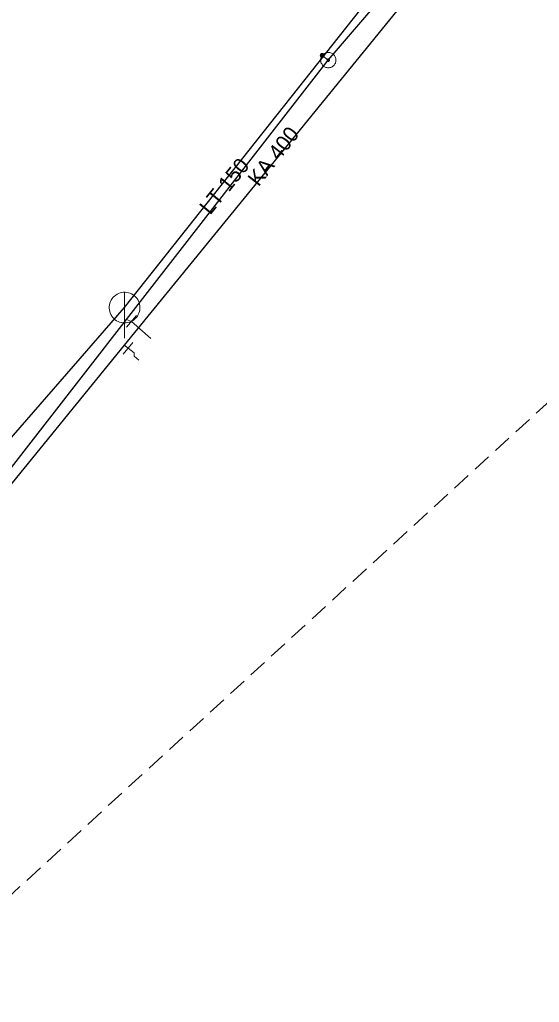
# Model space of a CAD drawing. Extents: x -790267 to -789874, y -989766 to -989454.
# Drawn here: x -790004.3 to -789970.5, y -989730.1 to -989666 of the extents above; entities that cross this region are included whole.
import ezdxf

# ---------------------------------------------------------------- set-up
doc = ezdxf.new("R2010")
doc.units = 0
doc.header["$LTSCALE"] = 0.4
doc.linetypes.add('MEDIUM_DASHED', pattern=[4.5, 3, -1.5])
doc.layers.add('1', color=7, linetype='Continuous')
for name, color, linetype, lineweight in [('13', 7, 'Continuous', 13), ('14', 7, 'Continuous', 13), ('17', 7, 'Continuous', 25), ('22', 7, 'Continuous', 13), ('34', 7, 'Continuous', 13), ('47', 7, 'Continuous', 13), ('63', 7, 'MEDIUM_DASHED', 25), ('9', 7, 'Continuous', 13)]:
    doc.layers.add(name, color=color, linetype=linetype, lineweight=lineweight)

msp = doc.modelspace()

# ---------------------------------------------------------------- linework, layer by layer
at = {"layer": '13'}
for points in [[(-789997.342, -989685.576), (-789997.024, -989685.702), (-789995.752, -989686.822)], [(-789997.247, -989687.449), (-789996.85, -989687.75), (-789996.85, -989687.96), (-789996.55, -989688.219)]]:
    msp.add_lwpolyline(points, dxfattribs=at)
at = {"layer": '14'}
for p, q in [((-789984.21, -989668.683), (-789984.603, -989668.375)), ((-789997.491, -989687.245), (-789997.247, -989687.449))]:
    msp.add_line(p, q, dxfattribs=at)
at = {"layer": '14', "lineweight": 25}
msp.add_lwpolyline([(-790015.27, -989747.72), (-790017.28, -989707.56), (-789997.47, -989684.8), (-789979.42, -989661.98), (-789971.89, -989652.27)], dxfattribs=at)
at = {"layer": '17'}
for points in [[(-789984.21, -989668.683), (-789974.678, -989657.539), (-789933.135, -989608.969)], [(-789973.42, -989657.67), (-789975.664, -989660.431), (-789977.556, -989662.759), (-789987.276, -989674.721), (-789997.491, -989687.245), (-790005.072, -989696.559), (-790016.278, -989710.509), (-790018.158, -989712.846), (-790025.949, -989722.546), (-790026.25, -989722.92), (-790028.329, -989725.546), (-790029.004, -989726.397), (-790029.656, -989727.219)], [(-790016.192, -989709.824), (-789997.342, -989685.576), (-789984.21, -989668.683)]]:
    msp.add_lwpolyline(points, dxfattribs=at)
at = {"layer": '22'}
msp.add_line((-789997.47, -989686.8), (-789997.469, -989683.8), dxfattribs=at)
msp.add_lwpolyline([(-789996.47, -989684.8), (-789996.475, -989684.691), (-789996.493, -989684.583), (-789996.523, -989684.477), (-789996.563, -989684.376), (-789996.615, -989684.279), (-789996.677, -989684.189), (-789996.749, -989684.106), (-789996.829, -989684.032), (-789996.917, -989683.966), (-789997.011, -989683.911), (-789997.111, -989683.866), (-789997.216, -989683.833), (-789997.323, -989683.811), (-789997.432, -989683.801), (-789997.542, -989683.803), (-789997.65, -989683.817), (-789997.757, -989683.842), (-789997.86, -989683.879), (-789997.958, -989683.928), (-789998.05, -989683.986), (-789998.136, -989684.055), (-789998.213, -989684.132), (-789998.282, -989684.218), (-789998.341, -989684.31), (-789998.389, -989684.408), (-789998.426, -989684.511), (-789998.452, -989684.618), (-789998.466, -989684.726), (-789998.469, -989684.836), (-789998.459, -989684.945), (-789998.438, -989685.052), (-789998.404, -989685.156), (-789998.36, -989685.256), (-789998.305, -989685.351), (-789998.239, -989685.439), (-789998.165, -989685.519), (-789998.082, -989685.591), (-789997.992, -989685.653), (-789997.896, -989685.705), (-789997.794, -989685.746), (-789997.689, -989685.776), (-789997.581, -989685.794), (-789997.471, -989685.8), (-789997.362, -989685.794), (-789997.254, -989685.776), (-789997.149, -989685.747), (-789997.047, -989685.706), (-789996.95, -989685.654), (-789996.86, -989685.592), (-789996.777, -989685.521), (-789996.702, -989685.441), (-789996.637, -989685.353), (-789996.581, -989685.259), (-789996.537, -989685.159), (-789996.503, -989685.055), (-789996.481, -989684.947), (-789996.471, -989684.838)], close=True, dxfattribs=at)
at = {"layer": '34'}
for p, q in [((-789996.693, -989685.326), (-789997.354, -989686.076)), ((-789996.927, -989687.064), (-789997.567, -989687.833))]:
    msp.add_line(p, q, dxfattribs=at)
at = {"layer": '47'}
for points in [[(-789983.918, -989668.276), (-789983.962, -989668.249), (-789984.009, -989668.225), (-789984.057, -989668.207), (-789984.108, -989668.193), (-789984.16, -989668.185), (-789984.213, -989668.183), (-789984.264, -989668.186), (-789984.316, -989668.195), (-789984.366, -989668.208), (-789984.415, -989668.227), (-789984.462, -989668.251), (-789984.505, -989668.28), (-789984.546, -989668.313), (-789984.583, -989668.35), (-789984.616, -989668.391), (-789984.643, -989668.435), (-789984.667, -989668.482), (-789984.686, -989668.531), (-789984.699, -989668.581), (-789984.707, -989668.633), (-789984.709, -989668.686), (-789984.706, -989668.738), (-789984.698, -989668.79), (-789984.685, -989668.84), (-789984.665, -989668.888), (-789984.641, -989668.935), (-789984.612, -989668.979), (-789984.579, -989669.019), (-789984.542, -989669.056), (-789984.501, -989669.089), (-789984.457, -989669.116), (-789984.41, -989669.14), (-789984.361, -989669.16), (-789984.311, -989669.172), (-789984.259, -989669.18), (-789984.207, -989669.183), (-789984.155, -989669.18), (-789984.103, -989669.172), (-789984.052, -989669.158), (-789984.004, -989669.138), (-789983.957, -989669.114), (-789983.913, -989669.086), (-789983.873, -989669.052), (-789983.836, -989669.015), (-789983.803, -989668.974), (-789983.776, -989668.93), (-789983.752, -989668.883), (-789983.733, -989668.835), (-789983.72, -989668.784), (-789983.712, -989668.732), (-789983.709, -989668.68), (-789983.713, -989668.628), (-789983.721, -989668.577), (-789983.735, -989668.526), (-789983.754, -989668.477), (-789983.778, -989668.43), (-789983.806, -989668.387), (-789983.84, -989668.346), (-789983.877, -989668.309)], [(-789984.162, -989668.616), (-789984.169, -989668.611), (-789984.177, -989668.608), (-789984.184, -989668.605), (-789984.193, -989668.602), (-789984.201, -989668.601), (-789984.21, -989668.601), (-789984.219, -989668.601), (-789984.227, -989668.602), (-789984.235, -989668.605), (-789984.243, -989668.608), (-789984.251, -989668.612), (-789984.258, -989668.617), (-789984.265, -989668.622), (-789984.271, -989668.627), (-789984.276, -989668.635), (-789984.281, -989668.642), (-789984.284, -989668.65), (-789984.287, -989668.657), (-789984.29, -989668.666), (-789984.291, -989668.674), (-789984.291, -989668.683), (-789984.291, -989668.692), (-789984.29, -989668.7), (-789984.288, -989668.709), (-789984.284, -989668.716), (-789984.28, -989668.724), (-789984.275, -989668.731), (-789984.27, -989668.738), (-789984.265, -989668.744), (-789984.257, -989668.749), (-789984.25, -989668.754), (-789984.242, -989668.757), (-789984.235, -989668.76), (-789984.226, -989668.763), (-789984.218, -989668.764), (-789984.21, -989668.765), (-789984.2, -989668.764), (-789984.192, -989668.763), (-789984.183, -989668.761), (-789984.176, -989668.757), (-789984.168, -989668.753), (-789984.161, -989668.748), (-789984.154, -989668.743), (-789984.148, -989668.738), (-789984.143, -989668.73), (-789984.138, -989668.723), (-789984.135, -989668.715), (-789984.132, -989668.708), (-789984.129, -989668.699), (-789984.128, -989668.691), (-789984.127, -989668.683), (-789984.128, -989668.673), (-789984.129, -989668.665), (-789984.132, -989668.657), (-789984.135, -989668.649), (-789984.139, -989668.641), (-789984.144, -989668.634), (-789984.149, -989668.627), (-789984.154, -989668.621)]]:
    msp.add_lwpolyline(points, close=True, dxfattribs=at)
at = {"layer": '63'}
msp.add_lwpolyline([(-790188.469, -989455.136), (-790139.344, -989496.446), (-790139.344, -989496.446), (-790029.929, -989518.217), (-790029.929, -989518.217), (-789963.498, -989555.061), (-789963.498, -989555.061), (-789946.75, -989559.527), (-789946.75, -989559.527), (-789908.79, -989634.89), (-789908.79, -989634.89), (-790051.142, -989765.519), (-790051.142, -989765.519), (-790157.208, -989714.719), (-790157.208, -989714.719), (-790153.3, -989672.851), (-790153.3, -989672.851), (-790266.065, -989576.274), (-790266.065, -989576.274), (-790235.362, -989502.586), (-790235.362, -989502.586), (-790189.028, -989455.694), (-790189.028, -989455.694)], close=True, dxfattribs=at)
at = {"layer": '9'}
for points in [[(-789984.729, -989668.375), (-789984.729, -989668.388), (-789984.727, -989668.401), (-789984.724, -989668.414), (-789984.719, -989668.426), (-789984.713, -989668.438), (-789984.706, -989668.449), (-789984.698, -989668.459), (-789984.688, -989668.469), (-789984.678, -989668.477), (-789984.667, -989668.484), (-789984.655, -989668.49), (-789984.643, -989668.495), (-789984.63, -989668.498), (-789984.617, -989668.5), (-789984.604, -989668.502), (-789984.591, -989668.501), (-789984.578, -989668.499), (-789984.565, -989668.496), (-789984.553, -989668.491), (-789984.541, -989668.485), (-789984.53, -989668.478), (-789984.52, -989668.47), (-789984.51, -989668.46), (-789984.502, -989668.45), (-789984.495, -989668.439), (-789984.489, -989668.427), (-789984.484, -989668.415), (-789984.481, -989668.402), (-789984.479, -989668.389), (-789984.477, -989668.376), (-789984.478, -989668.363), (-789984.48, -989668.35), (-789984.483, -989668.337), (-789984.488, -989668.325), (-789984.494, -989668.313), (-789984.501, -989668.302), (-789984.509, -989668.292), (-789984.519, -989668.282), (-789984.529, -989668.274), (-789984.54, -989668.267), (-789984.552, -989668.261), (-789984.564, -989668.256), (-789984.577, -989668.253), (-789984.59, -989668.251), (-789984.603, -989668.25), (-789984.616, -989668.25), (-789984.629, -989668.252), (-789984.642, -989668.255), (-789984.654, -989668.26), (-789984.666, -989668.266), (-789984.677, -989668.273), (-789984.687, -989668.281), (-789984.697, -989668.291), (-789984.705, -989668.301), (-789984.712, -989668.312), (-789984.718, -989668.324), (-789984.723, -989668.336), (-789984.726, -989668.349), (-789984.728, -989668.362)], [(-789984.709, -989668.375), (-789984.71, -989668.386), (-789984.708, -989668.397), (-789984.705, -989668.408), (-789984.701, -989668.418), (-789984.696, -989668.428), (-789984.69, -989668.437), (-789984.683, -989668.446), (-789984.675, -989668.454), (-789984.666, -989668.461), (-789984.657, -989668.467), (-789984.647, -989668.472), (-789984.637, -989668.476), (-789984.626, -989668.479), (-789984.615, -989668.482), (-789984.604, -989668.482), (-789984.593, -989668.482), (-789984.582, -989668.48), (-789984.571, -989668.477), (-789984.561, -989668.473), (-789984.551, -989668.468), (-789984.542, -989668.462), (-789984.533, -989668.455), (-789984.525, -989668.447), (-789984.518, -989668.438), (-789984.512, -989668.429), (-789984.507, -989668.419), (-789984.503, -989668.409), (-789984.5, -989668.398), (-789984.498, -989668.387), (-789984.497, -989668.376), (-789984.497, -989668.365), (-789984.499, -989668.354), (-789984.502, -989668.343), (-789984.506, -989668.333), (-789984.511, -989668.323), (-789984.517, -989668.314), (-789984.524, -989668.305), (-789984.532, -989668.297), (-789984.541, -989668.29), (-789984.55, -989668.284), (-789984.56, -989668.279), (-789984.57, -989668.275), (-789984.581, -989668.272), (-789984.592, -989668.27), (-789984.603, -989668.27), (-789984.614, -989668.269), (-789984.625, -989668.271), (-789984.636, -989668.274), (-789984.646, -989668.278), (-789984.656, -989668.283), (-789984.665, -989668.289), (-789984.674, -989668.296), (-789984.682, -989668.304), (-789984.689, -989668.313), (-789984.695, -989668.322), (-789984.7, -989668.332), (-789984.704, -989668.342), (-789984.707, -989668.353), (-789984.709, -989668.364)], [(-789984.69, -989668.375), (-789984.69, -989668.384), (-789984.689, -989668.393), (-789984.686, -989668.402), (-789984.683, -989668.41), (-789984.679, -989668.418), (-789984.674, -989668.426), (-789984.668, -989668.433), (-789984.662, -989668.439), (-789984.655, -989668.445), (-789984.647, -989668.45), (-789984.639, -989668.454), (-789984.631, -989668.457), (-789984.622, -989668.46), (-789984.613, -989668.461), (-789984.604, -989668.463), (-789984.595, -989668.462), (-789984.586, -989668.461), (-789984.577, -989668.458), (-789984.569, -989668.455), (-789984.561, -989668.451), (-789984.553, -989668.446), (-789984.546, -989668.44), (-789984.54, -989668.434), (-789984.534, -989668.427), (-789984.529, -989668.419), (-789984.525, -989668.411), (-789984.522, -989668.403), (-789984.519, -989668.394), (-789984.518, -989668.385), (-789984.516, -989668.376), (-789984.517, -989668.367), (-789984.518, -989668.358), (-789984.521, -989668.349), (-789984.524, -989668.341), (-789984.528, -989668.333), (-789984.533, -989668.325), (-789984.539, -989668.318), (-789984.545, -989668.312), (-789984.552, -989668.306), (-789984.56, -989668.301), (-789984.568, -989668.297), (-789984.576, -989668.294), (-789984.585, -989668.291), (-789984.594, -989668.29), (-789984.603, -989668.289), (-789984.612, -989668.289), (-789984.621, -989668.29), (-789984.63, -989668.293), (-789984.638, -989668.296), (-789984.646, -989668.3), (-789984.654, -989668.305), (-789984.661, -989668.311), (-789984.667, -989668.317), (-789984.673, -989668.324), (-789984.678, -989668.332), (-789984.682, -989668.34), (-789984.685, -989668.348), (-789984.688, -989668.357), (-789984.689, -989668.366)], [(-789984.67, -989668.375), (-789984.67, -989668.382), (-789984.669, -989668.389), (-789984.668, -989668.396), (-789984.665, -989668.402), (-789984.662, -989668.408), (-789984.658, -989668.414), (-789984.654, -989668.42), (-789984.649, -989668.425), (-789984.643, -989668.429), (-789984.637, -989668.433), (-789984.631, -989668.436), (-789984.625, -989668.439), (-789984.618, -989668.44), (-789984.611, -989668.443), (-789984.604, -989668.443), (-789984.597, -989668.443), (-789984.59, -989668.441), (-789984.583, -989668.44), (-789984.577, -989668.437), (-789984.57, -989668.434), (-789984.565, -989668.43), (-789984.559, -989668.426), (-789984.554, -989668.421), (-789984.55, -989668.415), (-789984.546, -989668.409), (-789984.543, -989668.403), (-789984.54, -989668.397), (-789984.538, -989668.39), (-789984.537, -989668.383), (-789984.536, -989668.376), (-789984.536, -989668.369), (-789984.537, -989668.362), (-789984.539, -989668.355), (-789984.542, -989668.349), (-789984.545, -989668.342), (-789984.549, -989668.337), (-789984.553, -989668.331), (-789984.558, -989668.326), (-789984.564, -989668.322), (-789984.569, -989668.318), (-789984.576, -989668.315), (-789984.582, -989668.312), (-789984.589, -989668.31), (-789984.596, -989668.309), (-789984.603, -989668.309), (-789984.61, -989668.309), (-789984.617, -989668.309), (-789984.624, -989668.311), (-789984.63, -989668.314), (-789984.636, -989668.317), (-789984.642, -989668.321), (-789984.648, -989668.325), (-789984.653, -989668.33), (-789984.657, -989668.336), (-789984.661, -989668.341), (-789984.664, -989668.348), (-789984.667, -989668.354), (-789984.668, -989668.361), (-789984.67, -989668.368)], [(-789984.65, -989668.375), (-789984.65, -989668.38), (-789984.65, -989668.385), (-789984.649, -989668.39), (-789984.647, -989668.394), (-789984.645, -989668.399), (-789984.642, -989668.403), (-789984.639, -989668.406), (-789984.635, -989668.41), (-789984.632, -989668.413), (-789984.628, -989668.416), (-789984.623, -989668.418), (-789984.619, -989668.42), (-789984.614, -989668.421), (-789984.609, -989668.423), (-789984.604, -989668.423), (-789984.599, -989668.423), (-789984.594, -989668.422), (-789984.589, -989668.421), (-789984.585, -989668.419), (-789984.58, -989668.417), (-789984.576, -989668.414), (-789984.572, -989668.411), (-789984.569, -989668.407), (-789984.566, -989668.404), (-789984.563, -989668.4), (-789984.561, -989668.395), (-789984.559, -989668.391), (-789984.558, -989668.386), (-789984.557, -989668.381), (-789984.556, -989668.376), (-789984.556, -989668.371), (-789984.557, -989668.366), (-789984.558, -989668.361), (-789984.56, -989668.357), (-789984.562, -989668.352), (-789984.565, -989668.348), (-789984.568, -989668.344), (-789984.571, -989668.341), (-789984.575, -989668.338), (-789984.579, -989668.335), (-789984.584, -989668.333), (-789984.588, -989668.331), (-789984.593, -989668.33), (-789984.598, -989668.329), (-789984.603, -989668.329), (-789984.608, -989668.329), (-789984.613, -989668.33), (-789984.618, -989668.33), (-789984.622, -989668.332), (-789984.627, -989668.334), (-789984.631, -989668.337), (-789984.634, -989668.34), (-789984.638, -989668.343), (-789984.641, -989668.347), (-789984.644, -989668.351), (-789984.646, -989668.356), (-789984.648, -989668.36), (-789984.649, -989668.365), (-789984.65, -989668.37)], [(-789984.63, -989668.375), (-789984.63, -989668.378), (-789984.631, -989668.381), (-789984.63, -989668.383), (-789984.629, -989668.386), (-789984.628, -989668.389), (-789984.626, -989668.391), (-789984.624, -989668.393), (-789984.622, -989668.395), (-789984.62, -989668.397), (-789984.618, -989668.399), (-789984.615, -989668.401), (-789984.612, -989668.402), (-789984.61, -989668.402), (-789984.607, -989668.403), (-789984.604, -989668.403), (-789984.601, -989668.403), (-789984.598, -989668.403), (-789984.595, -989668.402), (-789984.593, -989668.401), (-789984.59, -989668.4), (-789984.588, -989668.398), (-789984.585, -989668.396), (-789984.583, -989668.394), (-789984.582, -989668.392), (-789984.58, -989668.39), (-789984.579, -989668.387), (-789984.577, -989668.384), (-789984.577, -989668.382), (-789984.576, -989668.379), (-789984.575, -989668.376), (-789984.576, -989668.373), (-789984.576, -989668.37), (-789984.577, -989668.367), (-789984.578, -989668.365), (-789984.579, -989668.362), (-789984.581, -989668.36), (-789984.582, -989668.357), (-789984.584, -989668.355), (-789984.587, -989668.354), (-789984.589, -989668.352), (-789984.592, -989668.351), (-789984.594, -989668.35), (-789984.597, -989668.349), (-789984.6, -989668.349), (-789984.603, -989668.348), (-789984.606, -989668.349), (-789984.609, -989668.348), (-789984.611, -989668.35), (-789984.614, -989668.35), (-789984.617, -989668.351), (-789984.619, -989668.353), (-789984.621, -989668.354), (-789984.623, -989668.356), (-789984.625, -989668.359), (-789984.627, -989668.361), (-789984.628, -989668.364), (-789984.629, -989668.366), (-789984.63, -989668.369), (-789984.63, -989668.372)], [(-789984.611, -989668.375), (-789984.611, -989668.377), (-789984.611, -989668.377), (-789984.61, -989668.377), (-789984.61, -989668.379), (-789984.611, -989668.38), (-789984.609, -989668.38), (-789984.609, -989668.38), (-789984.609, -989668.382), (-789984.609, -989668.382), (-789984.608, -989668.383), (-789984.606, -989668.383), (-789984.606, -989668.383), (-789984.606, -989668.384), (-789984.604, -989668.384), (-789984.604, -989668.384), (-789984.603, -989668.384), (-789984.602, -989668.384), (-789984.602, -989668.383), (-789984.601, -989668.383), (-789984.599, -989668.383), (-789984.599, -989668.382), (-789984.599, -989668.382), (-789984.598, -989668.381), (-789984.598, -989668.381), (-789984.596, -989668.38), (-789984.596, -989668.379), (-789984.595, -989668.378), (-789984.595, -989668.378), (-789984.595, -989668.377), (-789984.595, -989668.376), (-789984.595, -989668.375), (-789984.595, -989668.374), (-789984.595, -989668.374), (-789984.596, -989668.373), (-789984.596, -989668.372), (-789984.597, -989668.371), (-789984.597, -989668.371), (-789984.598, -989668.37), (-789984.598, -989668.37), (-789984.599, -989668.369), (-789984.6, -989668.369), (-789984.601, -989668.368), (-789984.601, -989668.368), (-789984.602, -989668.368), (-789984.603, -989668.368), (-789984.604, -989668.368), (-789984.605, -989668.368), (-789984.605, -989668.368), (-789984.606, -989668.369), (-789984.607, -989668.368), (-789984.608, -989668.37), (-789984.608, -989668.37), (-789984.609, -989668.37), (-789984.609, -989668.37), (-789984.61, -989668.372), (-789984.61, -989668.373), (-789984.61, -989668.374), (-789984.611, -989668.374), (-789984.611, -989668.375)]]:
    msp.add_lwpolyline(points, close=True, dxfattribs=at)

# ---------------------------------------------------------------- texts
at = {"layer": '1'}
for s, rotation, p in [('KA 400', 52, (-789988.748, -989676.974)), ('LT 150', 51, (-789991.902, -989678.818))]:
    msp.add_text(s, height=1, rotation=rotation, dxfattribs=at).set_placement(p)

doc.saveas('drawing.dxf')
